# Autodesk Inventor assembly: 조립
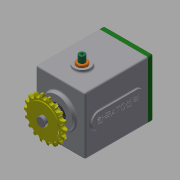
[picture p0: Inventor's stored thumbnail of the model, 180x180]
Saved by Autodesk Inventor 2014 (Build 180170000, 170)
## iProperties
Created: 2018-12
Part Number: 조립
Document SubType Name: Assembly
Designer: kh
Mass: 1863 g
Surface Area: 1968.34 cm^2
Volume: 815.226 cm^3
Density: 2.28526 g/cm^3
Author: kh
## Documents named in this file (16)
- C:\Users\kh\Desktop\381207V1011\조립.iam
- C:\Users\kh\Desktop\381207V1011\본체.ipt
- C:\Users\kh\Desktop\381207V1011\멈춤나사 M3x8.ipt
- C:\Users\kh\Desktop\381207V1011\메인 기어 축.ipt
- C:\Users\kh\Desktop\381207V1011\베어링 608.ipt
- C:\Users\kh\Desktop\381207V1011\베어링 6003.ipt
- C:\Users\kh\Desktop\381207V1011\볼트 M4 x 10.ipt
- C:\Users\kh\Desktop\381207V1011\부시.ipt
- C:\Users\kh\Desktop\381207V1011\서브 기어 축.ipt
- C:\Users\kh\Desktop\381207V1011\스프로킷.ipt
- C:\Users\kh\Desktop\381207V1011\슬라이더.ipt
- C:\Users\kh\Desktop\381207V1011\오일 실 8 22 7.ipt
- C:\Users\kh\Desktop\381207V1011\오일 실 17 32 8.ipt
- C:\Users\kh\Desktop\381207V1011\커버.ipt
- C:\Users\kh\Desktop\381207V1011\키 5 x 5 x 18.ipt
- C:\Users\kh\Desktop\381207V1011\가변스프링.ipt
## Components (1 placed, 1 different names)
1. 가변스프링:1 — Mate:6, Mate:7, Mate:8
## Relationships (3: Mate 3)
- Mate:6: 가변스프링:1
- Mate:7: 가변스프링:1
- Mate:8: 가변스프링:1
